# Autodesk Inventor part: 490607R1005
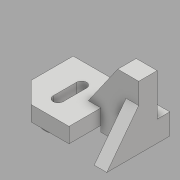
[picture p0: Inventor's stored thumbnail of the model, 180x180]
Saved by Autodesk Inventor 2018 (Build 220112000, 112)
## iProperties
Created: 2019-06
Part Number: 490607R1005
Material: 일반
Document SubType Name: Modeling
Designer: 6507_11
Density: 1 g/cm^3
Appearance: 기본값
Author: 6507_11
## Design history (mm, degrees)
sketch "스케치1"
  geometry: L1 (35, 37.5)-(-35, 37.5); L2 (-35, 37.5)-(-35, -12.5); L3 (-10, -37.5)-(35, -37.5); L4 (35, -37.5)-(35, 37.5); L5 (35, 37.5)-(-35, -37.5); L6 (-35, 37.5)-(35, -37.5); L7 (-10, -37.5)-(-35, -12.5); L8 (-35, 37.5)-(-35, -15.5); L9 (-35, -15.5)-(0, -15.5); L10 (6, 12.5)-(6, -15.5); L11 (-6, 12.5)-(-6, -15.5); A1 r 6 centre (0, -15.5) between (-6, -15.5) and (6, -15.5); A2 r 6 centre (0, 12.5) between (6, 12.5) and (-6, 12.5); 1 further point
  constraints: 22 end point, 4 point on circle, 3 parallel, 2 centre point, 2 midpoint, 2 perpendicular, 2 tangent, 1 coincident, 1 horizontal, 1 point on line, 1 vertical
  dimensions: "d0" = 70 distance of L3.end L5.end; "d1" = 75 distance of L5.end L1.end; "d3" = 45 deg angle of L3 L7; "d5" = 53 distance of L1.end L8.end; "d6" = 35 distance of L8.end L9.end; "d7" = 12 diameter of A1; "d9" = 12 diameter of A2
extrude "돌출1" new body sketch "스케치1" distance "d10" = 18; taper "d11" = 0 deg
sketch "스케치4"
  geometry: L1 (70, -18)-(0, -18) reference; L2 (70, 0)-(70, -18) reference; L3 (70, 0)-(70, 7); L4 (70, 7)-(115, 7); L5 (115, 7)-(115, -68); L6 (90, -68)-(115, -68); L7 (90, -68)-(54.99, -18); 1 further point
  constraints: 10 end point, 2 perpendicular, 1 horizontal, 1 point on line, 1 vertical
  dimensions: "d12" = 7 distance of L2.start L3.end; "d13" = 45 distance of L3.end L4.end; "d14" = 75 distance of L4.end L5.end; "d17" = 25 distance of L6.start L5.end
extrude "돌출2" join sketch "스케치4" distance "d19" = 37; taper "d20" = 0 deg
sketch "스케치7"
  geometry: L1 (0, -37)-(50, -37) reference; L2 (0, -37)-(25, -37); L3 (25, -37)-(75, -75); L4 (68, -37)-(75, -37) reference; L5 (75, -75)-(75, -37); L6 (75, -37)-(25, -37); 1 further point
  constraints: 8 end point, 2 perpendicular, 1 midpoint
extrude "돌출3" join sketch "스케치7" distance "d23" = 15; taper "d24" = 0 deg
sketch "스케치8"
  geometry: L1 (50, 0)-(0, 0) reference; L2 (50, -15)-(0, -15); L3 (0, -15)-(0, 0); L4 (0, 0)-(50, 0); L5 (50, 0)-(50, -15); 2 further points
  constraints: 8 end point, 2 parallel, 1 horizontal, 1 perpendicular
  dimensions: "d26" = 15 distance of L2.start L1.start
extrude "돌출4" cut sketch "스케치8" extent not by distance; stored distance "d27" = 15; taper "d28" = 0 deg
sketch "스케치9"
  geometry: C1 r 16 at (0, -15.5); C2 r 10 at (0, -15.5); A1 r 6 centre (0, -15.5) between (-6, -15.5) and (6, -15.5) reference; 1 further point
  constraints: 2 centre point, 2 coincident
  dimensions: "d29" = 32 diameter of C1; "d30" = 20 diameter of C2
extrude "돌출5" join sketch "스케치9" distance "d31" = 7; taper "d32" = 0 deg
node "솔리드1"
